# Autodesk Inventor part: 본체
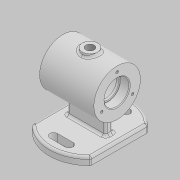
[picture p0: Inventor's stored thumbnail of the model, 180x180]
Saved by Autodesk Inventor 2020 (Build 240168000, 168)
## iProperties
Created: 2021-09
Part Number: 본체
Material: Generic
Document SubType Name: Modeling
Designer: Administrator
Density: 1 g/cm^3
Appearance: Default
Author: Administrator
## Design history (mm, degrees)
sketch "스케치1"
  geometry: L1 (0, 64.27)-(0, -64.27); L2 (37.5, 36.742)-(37.5, -36.742); L3 (-37.5, 36.742)-(-37.5, -36.742); A1 r 52.5 centre (0, 0) between (-37.5, -36.742) and (37.5, -36.742); A2 r 52.5 centre (0, 0) between (37.5, 36.742) and (-37.5, 36.742); 2 further points
  constraints: 6 end point, 4 point on circle, 3 coincident, 2 centre point, 2 parallel, 1 concentric, 1 midpoint, 1 vertical
  dimensions: "d2" = 37.5 distance between parallel lines of L1 L2; "d3" = 75 distance between parallel lines of L2 L3; "d4" = 52.5 radius of A2
extrude "돌출1" new body sketch "스케치1" distance "d5" = 10; taper "d6" = 0 deg
sketch "스케치2"
  geometry: L1 (0, 0)-(0, 127.647); L2 (35, 62)-(-35, 62); L3 (37.5, 0)-(-37.5, 0) reference; L4 (35, 92)-(-35, 92); L5 (20, 87)-(-20, 87); L6 (35, 78)-(23, 78); L7 (35, 92)-(35, 78); L8 (23, 78)-(23, 76); L9 (23, 76)-(20, 76); L10 (20, 87)-(20, 76); L11 (-35, 92)-(-35, 78); L12 (-35, 78)-(-23, 78); L13 (-23, 78)-(-23, 76); L14 (-23, 76)-(-20, 76); L15 (-20, 87)-(-20, 76); 2 further points
  constraints: 28 end point, 4 symmetric about line, 4 vertical, 3 horizontal, 2 midpoint, 2 parallel, 2 vertical alignment
  dimensions: "d7" = 62 distance between parallel lines of L3 L2; "d8" = 70 distance of L2.start L2.end; "d9" = 60 diameter of L4 L2; "d10" = 40 distance of L5.start L5.end; "d11" = 50 diameter of L5 L2; "d12" = 32 diameter of L6 L2; "d13" = 12 distance between parallel lines of L7 L8; "d14" = 28 diameter of L9 L2; "d15" = 3 distance of L8.end L9.end
revolve "회전1" sketch "스케치2" stored, may be unused: angle "d16" = 90 deg
sketch "스케치3"
  geometry: L1 (0, 0)-(0, 37); L2 (-5, 10)-(-5, 37.505); L3 (5, 10)-(5, 37.505); L4 (36.742, 10)-(-36.742, 10) reference; A1 r 25 centre (0, 62) between (-5, 37.505) and (0, 37) reference
  constraints: 6 end point, 3 point on circle, 2 parallel, 2 point on line, 1 vertical
  dimensions: "d17" = 5 distance between parallel lines of L2 L1; "d18" = 10 distance between parallel lines of L3 L2
extrude "돌출2" join sketch "스케치3" stored distance "d19" = 50; taper "d20" = 0 deg
sketch "스케치4"
  geometry: L1 (0, 0)-(0, 116.754); L2 (51.869, 62)-(-50.53, 62); L3 (37.5, 0)-(-37.5, 0) reference; L4 (10, 95)-(0, 95); L5 (10, 95)-(10, 87); L6 (20, 87)-(-20, 87) reference; 1 further point
  constraints: 8 end point, 2 point on line, 2 vertical, 1 horizontal, 1 parallel
  dimensions: "d21" = 62 distance between parallel lines of L2 L3; "d22" = 33 distance between parallel lines of L2 L4; "d25" = 20 diameter of L5 L1
revolve "회전2" sketch "스케치4" stored, may be unused: angle "d26" = 90 deg
sketch "스케치5"
  geometry: C1 r 10 at (0, 0) reference; 2 further points
  constraints: 1 coincident
hole "구멍1" sketch "스케치5" at (0, 0) diameter "d27" = 10.917; stored, may be unused: countersink angle "d31" = 90 deg, drill point angle "d33" = 118 deg; dims "d28" = 24, "d29" = 4, "d30" = 2, "d32" = 29.1
sketch "스케치6" dims "d34" = 46
  geometry: L1 (0, 0)-(-41.654, 0); C1 r 30 at (0, 0) reference; 3 further points
  constraints: 2 end point, 1 coincident, 1 horizontal, 1 horizontal alignment, 1 point on line, 2 other
hole "구멍2" sketch "스케치6" at (-23, 0) diameter "d35" = 3.45873; stored, may be unused: countersink angle "d39" = 90 deg, drill point angle "d41" = 118 deg; dims "d36" = 8, "d37" = 4, "d38" = 2, "d40" = 10
fillet "모깎기1" dims "d45" = 3, "d46" = 0.3
chamfer "모따기1" distance "d47" = 1; stored, may be unused: second distance "d48" = 2, angle "d49" = 45 deg
chamfer "모따기2" distance "d50" = 1; stored, may be unused: second distance "d51" = 2, angle "d52" = 45 deg
fillet "모깎기2" dims "d53" = 3
sketch "스케치7"
  geometry: L1 (0, 79.742)-(0, -79.742); L2 (-10, 79.742)-(-10, -79.742); L3 (10, 79.742)-(10, -79.742); L4 (-77.268, 0)-(77.268, 0); L5 (-77.268, 37)-(77.268, 37); L6 (-77.268, -37)-(77.268, -37); L7 (-10, 42)-(10, 42); L8 (-10, 32)-(10, 32); L9 (-10, -32)-(10, -31.863); L10 (-10, -42)-(10, -42.137); A1 r 5 centre (-10, -37) between (-10, -32) and (-10, -42); A2 r 5.137 centre (10, -37) between (9.93, -42.136) and (9.93, -31.864); A3 r 5 centre (-10, 37) between (-10, 42) and (-10, 32); A4 r 5 centre (10, 37) between (10, 32) and (10, 42); 3 further points
  constraints: 20 end point, 18 point on line, 10 point on circle, 4 centre point, 4 coincident, 4 parallel, 2 midpoint, 1 equal radius, 1 horizontal, 1 vertical
  dimensions: "d54" = 10 distance between parallel lines of L1 L2; "d55" = 20 distance between parallel lines of L2 L3; "d56" = 37 distance between parallel lines of L4 L5; "d57" = 37 distance between parallel lines of L4 L6; "d58" = 10 diameter of A1; "d59" = 10 diameter of A3
extrude "돌출3" cut sketch "스케치7" extent not by distance; stored distance "d60" = 0; taper "d61" = 0 deg
node "작업 평면1"
sketch "스케치8"
  geometry: L1 (-35, 32)-(-35, 92) reference; L2 (-35, 92)-(35, 92) reference; 2 further points
  constraints: 1 other
  dimensions: "d63" = 35 distance from line of point (0, 62) L1; "d64" = 30 distance from line of point (0, 62) L2
feature "엠보싱1" sketch "스케치8" dims "d65" = 0.5, "d66" = 0
node "솔리드1"
pattern_circular "원형 패턴1" dims angle "d43" = 360 deg
mirror "미러1"
feature "A9D066F2-1C7D-4E18-AEED-F7BC21143FA4" dims "d35" = 3.45873, "d36" = 8, "d37" = 4, "d38" = 2, "d39" = 90 deg, "d40" = 10, "d41" = 118 deg
other parameters: "d1" = 105, "d62" = 55.5
